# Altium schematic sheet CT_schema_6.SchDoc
size 221 x 258 mm
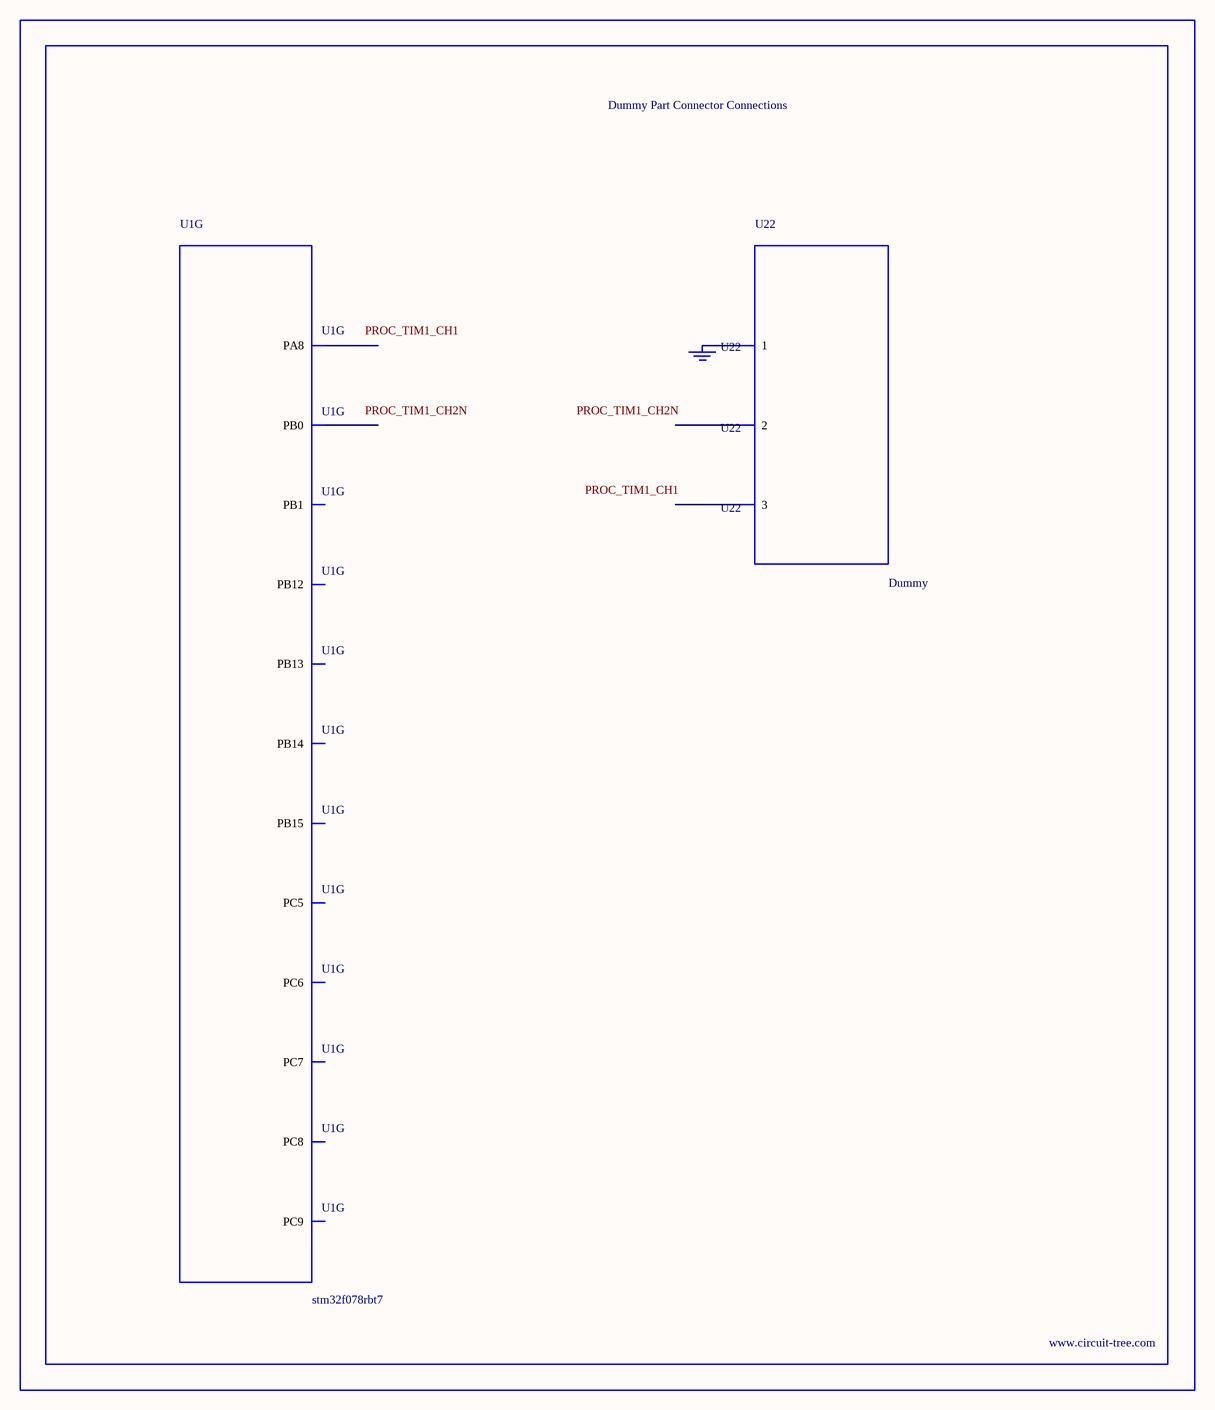
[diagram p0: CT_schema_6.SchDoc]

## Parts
BORDER5  (no value)
GND_INSTANCE_5_0  (no value)
U1  stm32f078rbt7  [LQFP64]  (part G of 7)
U22  Dummy  [DUMMY_PACKAGE_213]

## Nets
NetGND_INSTANCE_5_0_0: GND_INSTANCE_5_0.0(GND) U22.1

Not connected (* = marked no-connect by the designer): U1 25(PC5) 26(PB0) 27(PB1) 33(PB12) 34(PB13) 35(PB14) 36(PB15) 37(PC6) 38(PC7) 39(PC8) 40(PC9) 41(PA8); U22 2 3

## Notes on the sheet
- Labels drawn without touching a wire or pin: PROC_TIM1_CH1, PROC_TIM1_CH2N

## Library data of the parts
BORDER5 = BORDER_PAGE5
GND_INSTANCE_5_0 = GND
